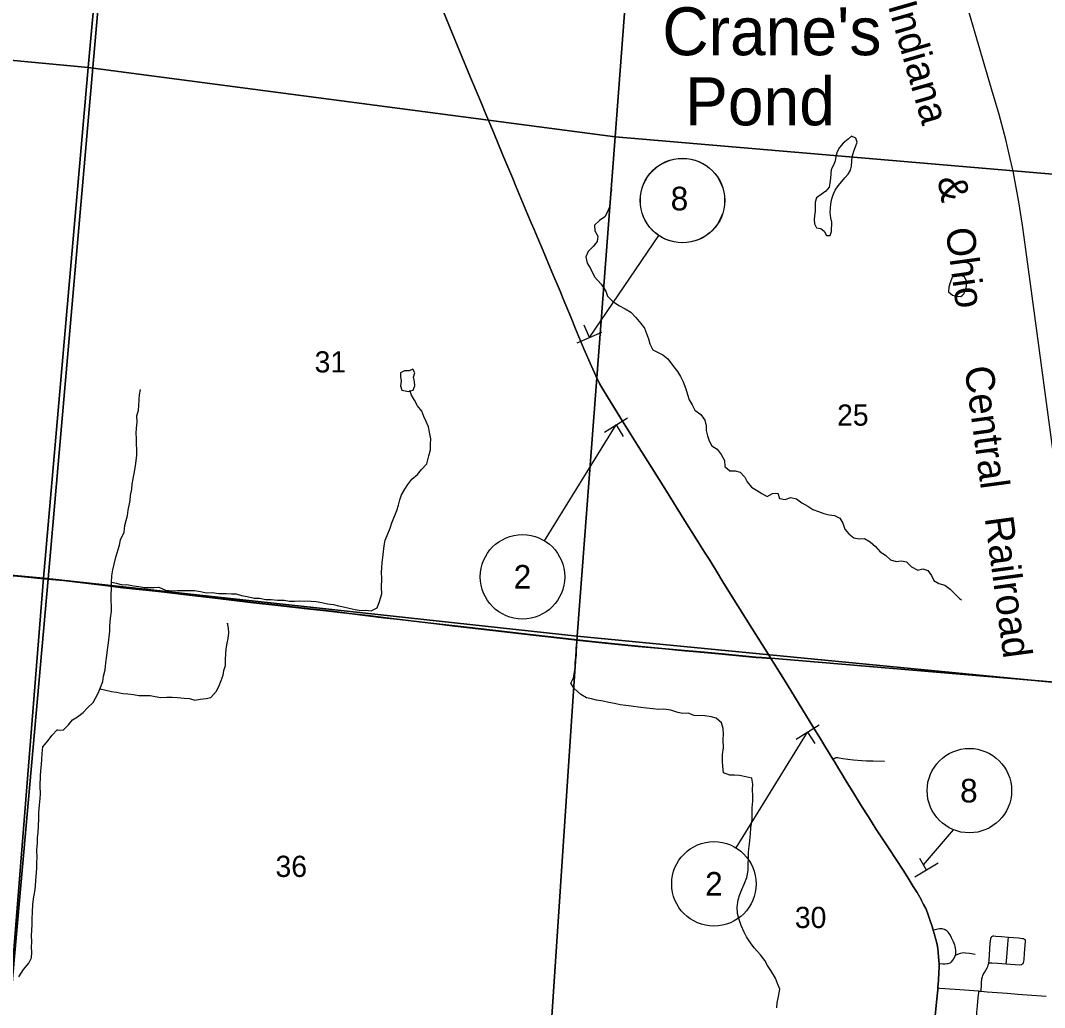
# Model space of a CAD drawing. Extents: x 0 to 1067, y 0 to 440.
# Drawn here: x 227.4 to 348.6, y 140.8 to 257.7 of the extents above; entities that cross this region are included whole.
import ezdxf

# ---------------------------------------------------------------- set-up
doc = ezdxf.new("R2010")
doc.units = 0
for name, color, linetype in [('Default', 7, 'Continuous'), ('GM_X_City_Street', 7, 'Continuous'), ('GM_X_County_Road', 7, 'Continuous'), ('GM_X_Minor_Lake', 7, 'Continuous'), ('GM_X_Minor_River', 7, 'Continuous'), ('GM_X_Minor_River_Text', 7, 'Continuous'), ('GM_X_Rail_Line', 7, 'Continuous'), ('GM_X_Rail_Line_Text', 7, 'Continuous'), ('GM_X_Section', 7, 'Continuous'), ('GM_X_Section_Text', 7, 'Continuous'), ('GM_X_State_Route', 7, 'Continuous'), ('GM_X_Township_Road', 7, 'Continuous'), ('SH_Masking', 7, 'Continuous'), ('SH_Text', 7, 'Continuous'), ('SN_P_Signs', 7, 'Continuous')]:
    doc.layers.add(name, color=color, linetype=linetype)

msp = doc.modelspace()

# ---------------------------------------------------------------- linework, layer by layer
at = {"layer": 'Default'}
for points in [[(282.18, 247.37), (281.7, 248.52), (280.7, 250.93), (279.4, 254.07), (278.48, 256.27), (277.48, 258.68), (276.56, 260.88), (275.71, 262.9), (275.33, 263.8), (274.26, 266.42), (272.12, 271.49), (271.32, 273.46), (270.51, 275.38), (269.76, 277.17), (268.97, 279.05), (268.49, 280.19), (265.98, 286.21), (264.67, 289.34), (263.99, 290.96), (262.45, 294.66), (261.91, 295.95)], [(308.93, 193.85), (308.38, 194.71), (307.38, 196.28), (305.87, 198.72), (303.87, 201.91), (302.14, 204.69), (300.44, 207.37), (298.67, 210.22), (296.91, 213.08), (296.23, 214.2), (295.97, 214.69), (295.51, 215.59), (295, 216.71), (294.11, 218.8), (293.13, 221.14), (292.59, 222.45), (291.65, 224.72), (291.29, 225.63), (290.32, 227.92), (289.07, 230.88), (288.6, 231.97), (288.21, 232.9), (287.88, 233.69), (287.42, 234.75), (286.05, 238.06), (285.68, 238.95), (284.53, 241.71), (283.41, 244.43), (282.32, 247.04), (282.18, 247.37)], [(314, 185.68), (310.69, 191), (309.7, 192.63), (308.93, 193.85)], [(316.25, 182.11), (315.96, 182.58), (314, 185.68)], [(325.94, 166.32), (325.27, 167.39), (324.93, 167.97), (324.64, 168.44), (324.25, 169.08), (323.81, 169.82), (323.59, 170.18), (323.27, 170.71), (322.47, 172.01), (322.11, 172.58), (321.34, 173.86), (319.89, 176.17), (317.86, 179.52), (316.61, 181.54), (316.25, 182.11)], [(332.17, 156.58), (331.89, 157.03), (330.23, 159.54), (329.29, 160.98), (328.74, 161.82), (328.34, 162.45), (327.79, 163.34), (327.5, 163.81), (326.86, 164.82), (325.94, 166.32)], [(336.14, 146.24), (336.14, 146.3), (336.1, 146.81), (336.05, 147.28), (336, 147.76), (335.92, 148.18), (335.91, 148.23), (335.78, 148.81), (335.58, 149.53), (335.47, 149.91), (335.33, 150.38), (335.03, 151.27), (334.78, 151.97), (334.57, 152.49), (334.33, 152.98), (334.09, 153.44), (334.03, 153.55), (333.55, 154.37), (333.09, 155.1), (332.48, 156.08), (332.17, 156.58)], [(336.05, 143.62), (336.07, 143.92), (336.14, 144.98), (336.15, 145.48), (336.15, 145.96), (336.15, 146.02), (336.14, 146.24)], [(335.65, 139.4), (335.84, 141.4), (335.99, 142.84), (336.02, 143.09), (336.05, 143.62)]]:
    msp.add_lwpolyline(points, dxfattribs=at)
at = {"layer": 'GM_X_City_Street'}
for points in [[(323.59, 170.18), (323.74, 170.27), (323.85, 170.32), (323.91, 170.34), (323.99, 170.36), (324.09, 170.37), (324.18, 170.37), (324.33, 170.35), (324.76, 170.27), (325.35, 170.18), (326.02, 170.11), (327.02, 170.03), (327.55, 170), (328.37, 169.97), (329.68, 169.96)], [(336.15, 145.96), (336.61, 145.95), (336.87, 145.95), (337.14, 145.96), (337.25, 145.97), (337.36, 146), (337.47, 146.04), (337.55, 146.1), (337.63, 146.18), (337.77, 146.36), (337.91, 146.55), (338.04, 146.8), (338.08, 146.91), (338.09, 146.96), (338.12, 147.09), (338.14, 147.31), (338.14, 147.57), (338.11, 147.79), (338.07, 147.98), (338.01, 148.15), (337.85, 148.53), (337.62, 149.01), (337.45, 149.37), (337.35, 149.52), (337.24, 149.67), (337.1, 149.8), (337, 149.87), (336.88, 149.95), (336.79, 150), (336.65, 150.05), (336.51, 150.08), (336.36, 150.09), (336.21, 150.08), (335.99, 150.04), (335.71, 149.97), (335.47, 149.91)], [(341.13, 142.7), (341.13, 142.81), (341.16, 143.42), (341.18, 143.77), (341.2, 144.04), (341.23, 144.19), (341.28, 144.38), (341.34, 144.55), (341.39, 144.67), (341.52, 144.93), (341.85, 145.48), (341.92, 145.62), (341.98, 145.8), (342.03, 146.03), (342.07, 146.32), (342.16, 147.67), (342.22, 148.44), (342.27, 148.88), (342.3, 149.02), (342.35, 149.11), (342.41, 149.18), (342.48, 149.23), (342.54, 149.25), (342.64, 149.25), (342.88, 149.23), (343.53, 149.17), (344.36, 149.1), (345.54, 149), (346.02, 148.95), (346.15, 148.92), (346.24, 148.88), (346.3, 148.82), (346.33, 148.77), (346.34, 148.71), (346.34, 148.6), (346.28, 147.67), (346.24, 147.15), (346.2, 146.47), (346.16, 146.23), (346.12, 146.06), (346.07, 145.95), (346.01, 145.88), (345.95, 145.84), (345.87, 145.81), (345.73, 145.8), (344.62, 145.87), (344.1, 145.9), (343.06, 145.96), (342.39, 146.01), (342.03, 146.03)], [(344.1, 145.9), (344.13, 146.24), (344.2, 147.24), (344.28, 148.24), (344.32, 148.72), (344.36, 149.1)], [(338.09, 146.96), (338.37, 147.08), (338.7, 147.2), (338.89, 147.25), (339.07, 147.27), (339.29, 147.26), (339.74, 147.2), (340.44, 147.09)], [(336.02, 143.09), (336.22, 143.07), (338.06, 142.93), (340.82, 142.73), (340.86, 142.72), (341.13, 142.7), (341.86, 142.64), (343.04, 142.53), (344.2, 142.45), (345.08, 142.38), (345.49, 142.35), (346.6, 142.27), (348.83, 142.12)], [(339.62, 129.86), (339.65, 130.08), (339.7, 130.47), (339.78, 131.21), (339.88, 132.06), (340.01, 133.28), (340.05, 133.72), (340.07, 134.02), (340.13, 134.74), (340.26, 136.27), (340.37, 137.57), (340.41, 137.97), (340.45, 138.38), (340.51, 138.97), (340.57, 139.45), (340.64, 140.16), (340.71, 140.95), (340.8, 141.96), (340.85, 142.49), (340.86, 142.72)]]:
    msp.add_lwpolyline(points, dxfattribs=at)
at = {"layer": 'GM_X_County_Road'}
for points in [[(191.36, 194.99), (191.68, 194.96), (194.01, 194.75), (196.91, 194.48), (198.76, 194.31), (200.99, 194.09), (202.58, 193.92), (204.21, 193.75), (204.9, 193.67), (205.88, 193.59), (208.15, 193.47), (208.82, 193.43), (212.46, 193.13), (214.73, 192.93), (218.89, 192.56), (221.63, 192.32), (226.05, 191.92), (227.5, 191.8), (229.8, 191.59), (230.71, 191.51)], [(230.71, 191.51), (231.11, 191.47), (232.51, 191.33), (234.47, 191.09), (237.43, 190.74), (239.51, 190.49), (243.77, 190.02), (247.36, 189.61), (250.47, 189.24), (254.65, 188.75), (258.25, 188.34), (261.69, 187.95), (263.58, 187.74), (264.91, 187.58), (266.36, 187.42), (268.54, 187.15), (270.39, 186.93), (271.98, 186.75), (276.01, 186.27), (278.82, 185.94), (284.71, 185.25), (286.37, 185.06), (291.6, 184.46), (293.63, 184.24)], [(293.63, 184.24), (295.12, 184.08), (297.38, 183.84), (300.53, 183.54), (303.35, 183.27), (306.04, 183.03)], [(306.04, 183.03), (307.03, 182.94), (308.36, 182.82)], [(308.36, 182.82), (310.48, 182.62), (314.5, 182.24), (315.18, 182.2), (316.25, 182.11)]]:
    msp.add_lwpolyline(points, dxfattribs=at)
at = {"layer": 'GM_X_Minor_Lake'}
for points in [[(325.78, 243.96), (325.39, 243.62), (324.79, 243.13), (324.37, 242.61), (324.09, 242.12), (323.93, 241.57), (323.85, 241.05), (323.71, 240.6), (323.4, 240.03), (323.35, 239.49), (323.32, 238.99), (323.22, 238.42), (323.14, 237.94), (322.73, 237.47), (322.18, 237.07), (321.63, 236.65), (321.48, 236.17), (321.5, 235.67), (321.49, 235.08), (321.41, 234.53), (321.38, 234.08), (321.42, 233.58), (321.64, 233.1), (322.16, 233.04), (322.56, 232.7), (322.83, 232.22), (323.13, 232.2)], [(323.13, 232.2), (323.28, 232.19), (323.43, 232.68), (323.44, 233.78), (323.34, 234.3), (323.28, 234.94), (323.31, 235.42), (323.34, 235.96), (323.44, 236.55), (323.61, 237.03), (323.84, 237.59), (324.19, 238.07), (324.63, 238.58), (324.98, 239.05), (325.39, 239.48), (325.65, 239.93), (325.77, 240.41), (325.82, 241), (325.86, 241.54), (326.05, 242.18), (326.28, 242.72), (326.47, 243.24), (326.32, 243.74), (325.78, 243.96)], [(337.7, 227.26), (337.47, 226.58), (337.32, 226.08), (337.27, 225.52), (337.74, 225.14), (338.24, 225), (338.73, 224.97), (338.94, 225.15)], [(338.94, 225.15), (339.1, 225.28), (339.31, 225.78), (339.39, 226.28), (339.4, 226.78), (339.16, 227.31), (338.66, 227.47), (338.16, 227.44), (337.7, 227.26)], [(273.07, 216.18), (272.89, 216.17), (272.39, 215.95), (272.41, 215.5), (272.47, 214.95), (272.39, 214.4), (272.56, 213.88), (273.33, 213.71)], [(273.33, 213.71), (273.88, 213.9), (274.09, 214.4), (274.05, 214.9), (273.95, 215.43), (274.09, 215.95), (273.87, 216.38), (273.41, 216.19), (273.07, 216.18)]]:
    msp.add_lwpolyline(points, dxfattribs=at)
at = {"layer": 'GM_X_Minor_River'}
for points in [[(297.36, 237.69), (297.27, 236.94), (297.21, 236.3), (297.17, 235.66), (296.92, 234.99), (296.58, 234.4), (295.96, 233.99), (295.37, 233.41), (295.42, 232.77), (295.74, 232.14), (295.66, 231.48), (295.21, 230.9), (294.62, 230.3), (294.33, 229.69), (294.51, 228.91), (294.88, 228.31), (295.35, 227.31), (296.17, 226.42), (296.69, 225.63), (296.9, 225.02), (297.48, 224.44), (298.26, 223.91), (298.98, 223.5), (299.67, 223.11), (300.24, 222.48), (300.84, 221.8), (301.28, 221.22), (301.51, 220.59), (301.76, 219.97), (301.91, 219.37), (302.25, 218.67), (302.83, 218.38), (303.44, 218.07), (304.06, 217.59), (304.72, 216.7), (305.2, 216.09), (305.53, 215.49), (305.87, 214.86), (306.17, 214.03), (306.38, 213.36), (306.59, 212.74), (306.91, 212.14), (307.26, 211.51), (307.97, 210.99), (308.43, 210.35), (308.57, 209.67), (308.6, 209.09), (308.76, 208.49), (308.95, 207.89), (309.25, 207.31), (309.9, 206.88), (310.36, 206.28), (310.77, 205.56), (310.79, 204.85), (311.37, 204.35), (312.03, 204.33), (312.62, 204.17), (313.15, 203.59), (313.43, 203.01), (313.96, 202.4), (314.56, 202.06), (315.19, 201.65), (315.79, 201.29), (316.44, 201.66), (317.06, 201.69), (317.26, 201.04), (317.94, 200.93), (318.59, 201.16), (319.27, 201.01), (319.91, 200.53), (320.61, 200.14), (321.23, 199.76), (321.89, 199.51), (322.5, 199.29), (323.15, 199.11), (323.79, 199.04), (324.39, 198.71), (324.78, 198.12), (325.01, 197.43), (325.48, 196.85), (326.08, 196.39), (326.69, 196.26), (327.33, 196.31), (327.98, 195.93), (328.62, 195.36), (329.19, 194.75), (329.82, 194.36), (330.4, 193.8), (331.07, 193.59), (331.69, 193.69), (332.28, 193.56), (332.9, 192.95), (333.64, 192.58), (334.23, 192.72), (334.82, 192.54), (335.24, 191.92), (335.54, 191.34), (336.12, 190.98), (336.84, 190.77), (337.47, 190.3), (338.04, 189.78)], [(231.73, 173.62), (232.51, 173.64), (233.08, 174.26), (233.55, 174.84), (234.17, 175.19), (234.85, 175.69), (235.35, 176.27), (236, 176.89), (236.34, 177.48), (236.63, 178.06), (236.9, 178.67), (237.14, 179.39), (237.25, 180.03), (237.43, 180.76), (237.53, 181.6), (237.62, 182.46), (237.73, 183.12), (237.82, 183.97), (238, 185.33), (237.99, 185.9), (238.07, 186.88), (238.18, 187.66), (238.2, 188.27), (238.15, 188.98), (238.15, 189.65), (238.19, 190.4), (238.17, 191.11), (238.22, 191.91), (238.35, 192.59), (238.51, 193.29), (238.69, 194.09), (239.14, 195.53), (239.25, 196.15), (239.69, 197.07), (239.75, 197.85), (239.91, 198.44), (240.09, 199.05), (240.15, 199.66), (240.41, 200.8), (240.43, 201.39), (240.59, 202.16), (240.63, 202.76), (240.76, 203.37), (240.93, 204.46), (241.06, 205.21), (241.18, 206.19), (241.18, 206.81), (241.13, 207.54), (241.13, 208.2), (241.1, 208.77), (241.16, 209.39), (241.23, 210.1), (241.2, 210.85), (241.38, 211.51), (241.42, 212.08), (241.47, 212.76), (241.48, 213.33), (241.61, 213.97)], [(238.17, 191.16), (238.78, 191.04), (239.44, 190.84), (240.01, 190.85), (240.8, 190.69), (241.43, 190.64), (242.07, 190.51), (242.64, 190.52), (243.21, 190.5), (243.8, 190.55), (244.59, 190.18), (245.38, 190.12), (245.95, 190.14), (246.63, 190.15), (247.2, 190.17), (248.02, 190.15), (248.72, 190.02), (249.45, 189.9), (250.09, 189.93), (250.9, 189.79), (251.75, 189.81), (252.38, 189.77), (252.95, 189.75), (253.56, 189.55), (254.26, 189.44), (255.08, 189.25), (255.71, 189.24), (256.44, 189.1), (257.1, 189.08), (257.83, 189.01), (258.62, 189.01), (259.26, 188.9), (259.85, 188.91), (260.49, 188.93), (261.83, 188.89), (262.42, 188.85), (263.08, 188.74), (263.76, 188.58), (264.46, 188.49), (265.07, 188.36), (265.66, 188.21), (266.34, 188.05), (267.04, 187.92), (267.74, 187.8), (268.31, 187.81), (268.92, 187.74), (269.64, 188.11), (269.93, 188.86), (270.19, 189.76), (270.16, 190.5), (270.17, 191.59), (270.15, 192.3), (270.19, 192.87), (270.21, 193.44), (270.35, 194.44), (270.45, 195.45), (270.58, 196.1), (270.8, 196.69), (271.17, 197.53), (271.39, 198.16), (271.98, 199.65), (272.18, 200.28), (272.31, 200.9), (272.51, 201.48), (272.9, 202.14), (273.25, 202.72), (273.75, 203.34), (274.4, 203.9), (274.88, 204.48), (275.51, 205.17), (275.77, 206.09), (275.95, 206.82), (275.94, 207.48), (275.99, 208.14), (275.83, 208.9), (275.71, 209.55), (275.43, 210.17), (275.17, 210.77), (274.94, 211.38), (274.41, 212.03), (274.05, 212.7), (273.7, 213.29), (273.51, 213.84)], [(338.04, 189.78), (338.57, 189.19), (338.82, 189.04)], [(236.83, 178.52), (237.52, 178.35), (238.18, 178.2), (238.79, 178.11), (239.52, 177.95), (240.11, 177.93), (240.79, 177.84), (241.42, 177.73), (242.17, 177.73), (242.76, 177.72), (243.35, 177.61), (244.03, 177.5), (244.72, 177.54), (245.35, 177.53), (246.01, 177.48), (246.79, 177.39), (247.4, 177.37), (248.05, 177.17), (248.69, 177.27), (249.38, 177.36), (249.95, 177.5), (250.59, 178.21), (250.9, 178.8), (251.17, 179.5), (251.4, 180.11), (251.48, 180.68), (251.68, 181.29), (251.68, 181.98), (251.72, 182.66), (251.74, 183.25), (251.89, 183.91), (251.98, 184.48), (252.07, 185.14), (252.04, 185.71), (251.92, 186.29), (251.92, 186.22)], [(310.61, 172.5), (310.64, 173.13), (310.59, 173.82), (310.41, 174.49), (309.76, 175.03), (309.18, 175.19), (308.43, 175.33), (307.16, 175.36), (306.46, 175.64), (305.82, 175.59), (305.21, 175.72), (304.4, 175.97), (303.56, 176.11), (302.92, 176.08), (302.31, 176.15), (301.53, 176.24), (300.85, 176.28), (299.72, 176.45), (299.08, 176.52), (298.4, 176.63), (297.73, 176.79), (297.07, 176.88), (296.37, 177.06), (295.6, 177.15), (295.01, 177.32), (294.4, 177.46), (293.73, 177.84), (292.97, 178.53), (292.56, 179.18), (292.87, 179.81), (292.98, 180.47), (293.12, 181.11), (293.06, 181.68), (293.22, 182.45), (293.24, 183.09), (293.18, 183.43)], [(227.21, 144.41), (227.75, 145.27), (228.38, 146.03), (228.71, 146.66), (228.77, 147.34), (228.71, 147.91), (228.74, 148.53), (228.73, 149.28), (228.74, 149.87), (228.78, 150.62), (228.81, 151.28), (228.83, 152.04), (228.89, 152.95), (228.97, 153.63), (229.1, 154.52), (229.2, 155.11), (229.24, 155.83), (229.3, 156.72), (229.33, 157.29), (229.34, 157.97), (229.37, 158.54), (229.34, 159.39), (229.43, 160.27), (229.44, 160.89), (229.52, 161.46), (229.55, 162.28), (229.59, 163.12), (229.6, 163.87), (229.67, 164.74), (229.75, 165.51), (229.76, 166.08), (229.75, 166.99), (229.77, 168.22), (229.83, 168.81), (229.89, 169.56), (229.92, 170.13), (229.96, 170.86), (230.04, 171.63), (230.67, 172.4), (231.13, 172.98), (231.81, 173.71)], [(314.11, 165.79), (314.05, 166.58), (314.09, 167.22), (313.98, 167.91), (313.28, 168.08), (312.53, 168.23), (311.94, 168.28), (311.37, 168.29), (310.65, 168.56), (310.57, 169.31), (310.51, 169.95), (310.5, 170.75), (310.63, 171.54), (310.61, 172.5)], [(316.95, 140.72), (317, 141.33), (317.15, 142.06), (317.3, 142.92), (317.04, 143.59), (316.78, 144.23), (316.25, 145.13), (315.85, 145.73), (315.52, 146.35), (315.03, 147), (314.25, 147.83), (313.82, 148.41), (313.36, 149.12), (313.09, 149.69), (312.74, 150.47), (312.46, 151.3), (312.29, 151.9), (312.24, 152.67), (312.39, 153.51), (312.56, 154.15), (312.8, 154.73), (313.1, 155.39), (313.41, 156.18), (313.56, 156.98), (313.55, 157.68), (313.59, 158.55), (313.58, 159.21), (313.71, 160.16), (313.82, 161.35), (313.88, 162.05), (314.01, 163.05), (314.04, 164.4), (314.1, 165.19), (314.11, 165.79)]]:
    msp.add_lwpolyline(points, dxfattribs=at)
at = {"layer": 'GM_X_Rail_Line'}
msp.add_lwpolyline([(350.64, 199.23), (347.49, 222.67), (346.44, 230.55), (346.07, 233.15), (345.64, 235.97), (344.96, 239.62), (344.47, 241.85), (344.05, 243.57), (343.26, 246.52), (342.37, 249.57), (338.22, 263.74)], dxfattribs=at)
at = {"layer": 'GM_X_Section'}
for points in [[(180.98, 316.33), (240.78, 310.99), (235.41, 252.1), (175.45, 257.74)], [(240.78, 310.99), (302.42, 305.21), (297.82, 243.9), (235.41, 252.1)], [(302.42, 305.21), (365.53, 299.9), (359.76, 238.61), (297.82, 243.9)], [(175.45, 257.74), (235.41, 252.1), (230.14, 191.62), (169.87, 197.13)], [(235.41, 252.1), (297.82, 243.9), (293.3, 184.74), (230.14, 191.62)], [(359.76, 238.61), (353.18, 178.94), (293.3, 184.74), (297.82, 243.9)], [(169.87, 197.13), (230.14, 191.62), (225.32, 131.25), (164.67, 136.08)], [(230.14, 191.62), (293.3, 184.74), (289.36, 125.48), (225.32, 131.25)], [(293.3, 184.74), (353.18, 178.94), (348.26, 119.58), (289.36, 125.48)]]:
    msp.add_lwpolyline(points, close=True, dxfattribs=at)
at = {"layer": 'GM_X_State_Route'}
for points in [[(261.91, 295.95), (262.45, 294.66), (263.99, 290.96), (264.67, 289.34), (265.98, 286.21), (268.49, 280.19), (268.97, 279.05), (269.76, 277.17), (270.51, 275.38), (271.32, 273.46), (272.12, 271.49), (274.26, 266.42), (275.33, 263.8), (275.71, 262.9), (276.56, 260.88), (277.48, 258.68), (278.48, 256.27), (279.4, 254.07), (280.7, 250.93), (281.7, 248.52), (282.18, 247.37)], [(282.18, 247.37), (282.32, 247.04), (283.41, 244.43), (284.53, 241.71), (285.68, 238.95), (286.05, 238.06), (287.42, 234.75), (287.88, 233.69), (288.21, 232.9), (288.6, 231.97), (289.07, 230.88), (290.32, 227.92), (291.29, 225.63), (291.65, 224.72), (292.59, 222.45), (293.13, 221.14), (294.11, 218.8), (295, 216.71), (295.51, 215.59), (295.97, 214.69), (296.23, 214.2), (296.91, 213.08), (298.67, 210.22), (300.44, 207.37), (302.14, 204.69), (303.87, 201.91), (305.87, 198.72), (307.38, 196.28), (308.38, 194.71), (308.93, 193.85)], [(308.93, 193.85), (309.7, 192.63), (310.69, 191), (314, 185.68)], [(314, 185.68), (315.96, 182.58), (316.25, 182.11)], [(316.25, 182.11), (316.61, 181.54), (317.86, 179.52), (319.89, 176.17), (321.34, 173.86), (322.11, 172.58), (322.47, 172.01), (323.27, 170.71), (323.59, 170.18), (323.81, 169.82), (324.25, 169.08), (324.64, 168.44), (324.93, 167.97), (325.27, 167.39), (325.94, 166.32)], [(325.94, 166.32), (326.86, 164.82), (327.5, 163.81), (327.79, 163.34), (328.34, 162.45), (328.74, 161.82), (329.29, 160.98), (330.23, 159.54), (331.89, 157.03), (332.17, 156.58)], [(332.17, 156.58), (332.48, 156.08), (333.09, 155.1), (333.55, 154.37), (334.03, 153.55), (334.09, 153.44), (334.33, 152.98), (334.57, 152.49), (334.78, 151.97), (335.03, 151.27), (335.33, 150.38), (335.47, 149.91), (335.58, 149.53), (335.78, 148.81), (335.91, 148.23), (335.92, 148.18), (336, 147.76), (336.05, 147.28), (336.1, 146.81), (336.14, 146.3), (336.14, 146.24)], [(336.14, 146.24), (336.15, 146.02), (336.15, 145.96), (336.15, 145.48), (336.14, 144.98), (336.07, 143.92), (336.05, 143.62)], [(336.05, 143.62), (336.02, 143.09), (335.99, 142.84), (335.84, 141.4), (335.65, 139.4)]]:
    msp.add_lwpolyline(points, dxfattribs=at)
at = {"layer": 'GM_X_Township_Road'}
for points in [[(226.04, 191.96), (227.49, 191.83), (229.79, 191.63), (230.69, 191.54), (241.1, 310.88), (247.73, 377.87), (252.4, 425.11), (131, 425.11)], [(241.1, 310.88), (230.69, 191.54), (231.1, 191.5), (232.5, 191.36), (234.46, 191.12), (237.42, 190.77), (239.49, 190.53), (243.75, 190.05), (247.35, 189.64), (250.46, 189.27), (254.64, 188.79), (258.23, 188.37), (261.68, 187.98), (263.57, 187.77), (264.9, 187.62), (266.34, 187.45), (268.53, 187.18), (270.37, 186.97), (271.96, 186.78), (275.99, 186.3), (278.81, 185.97), (284.69, 185.29), (286.36, 185.09), (291.58, 184.5), (295.1, 184.11), (297.36, 183.88), (300.51, 183.57), (303.33, 183.3), (306.03, 183.06), (307.01, 182.97), (308.34, 182.85), (310.47, 182.65), (314.48, 182.28), (315.16, 182.23), (316.24, 182.14), (353.13, 179.01)], [(225.27, 130.85), (230.69, 191.54), (229.79, 191.63), (227.49, 191.83), (226.04, 191.96)], [(353.13, 179.01), (316.24, 182.14), (315.16, 182.23), (314.48, 182.28), (310.47, 182.65), (308.34, 182.85), (307.01, 182.97), (306.03, 183.06), (303.33, 183.3), (300.51, 183.57), (297.36, 183.88), (295.1, 184.11), (291.58, 184.5), (286.36, 185.09), (284.69, 185.29), (278.81, 185.97), (275.99, 186.3), (271.96, 186.78), (270.37, 186.97), (268.53, 187.18), (266.34, 187.45), (264.9, 187.62), (263.57, 187.77), (261.68, 187.98), (258.23, 188.37), (254.64, 188.79), (250.46, 189.27), (247.35, 189.64), (243.75, 190.05), (239.49, 190.53), (237.42, 190.77), (234.46, 191.12), (232.5, 191.36), (231.1, 191.5), (230.69, 191.54), (225.27, 130.85)]]:
    msp.add_lwpolyline(points, dxfattribs=at)
at = {"layer": 'SH_Masking'}
for centre in [(305.79, 236.34), (286.84, 191.78), (339.74, 166.45), (309.5, 155.41)]:
    msp.add_circle(centre, 5, dxfattribs=at)
at = {"layer": 'SH_Text'}
for p, q in [((294.78, 220.12), (302.96, 232.21)), ((289.46, 196.03), (297.92, 209.76)), ((312.12, 159.67), (320.59, 173.39)), ((334.3, 157.68), (337.87, 161.81))]:
    msp.add_line(p, q, dxfattribs=at)
for centre in [(305.77, 236.35), (286.84, 191.78), (339.74, 166.45), (309.5, 155.41)]:
    msp.add_circle(centre, 5, dxfattribs=at)
at = {"layer": 'SN_P_Signs'}
for p, q in [((293.31, 219.49), (296.25, 220.75)), ((294.78, 220.12), (294.15, 221.59)), ((296.56, 208.91), (299.28, 210.6)), ((297.92, 209.76), (298.77, 208.4)), ((319.23, 172.55), (321.95, 174.24)), ((320.59, 173.39), (321.43, 172.03)), ((336.06, 157.85), (333.3, 156.22)), ((334.68, 157.03), (333.87, 158.41))]:
    msp.add_line(p, q, dxfattribs=at)

# ---------------------------------------------------------------- texts
at = {"layer": 'GM_X_Minor_River_Text'}
for s, rotation, p in [("Crane's", 0.0153, (303.39, 253.55)), ('Pond', 0.015, (306.08, 245.25))]:
    msp.add_text(s, height=5.682, rotation=rotation, dxfattribs=at).set_placement(p)
at = {"layer": 'GM_X_Rail_Line_Text'}
for s, height, rotation, p in [('Indiana', 3.398, 285.9979, (330.08, 259.45)), ('&', 3.4, 280.2148, (335.95, 238.96)), ('Ohio', 3.398, 277.7747, (336.91, 232.94)), ('Central', 3.398, 277.734, (339.15, 216.55)), ('Railroad', 3.398, 277.6445, (341.55, 198.76))]:
    msp.add_text(s, height=height, rotation=rotation, dxfattribs=at).set_placement(p)
at = {"layer": 'GM_X_Section_Text'}
for s, p in [('31', (262.23, 215.98)), ('25', (324.08, 209.68)), ('36', (257.6, 156.23)), ('30', (319.08, 150.18))]:
    msp.add_text(s, height=2.511, rotation=0, dxfattribs=at).set_placement(p)
at = {"layer": 'SH_Text'}
msp.add_text('8', height=2.8, rotation=360, dxfattribs=at).set_placement((304.38, 235.18))
for s, p in [('2', (285.79, 190.38)), ('8', (338.64, 165.05)), ('2', (308.46, 154.01))]:
    msp.add_text(s, height=2.8, dxfattribs=at).set_placement(p)

doc.saveas('drawing.dxf')
